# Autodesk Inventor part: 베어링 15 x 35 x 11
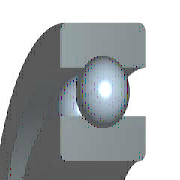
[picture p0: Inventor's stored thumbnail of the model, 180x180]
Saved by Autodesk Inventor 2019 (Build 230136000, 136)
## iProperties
Created: 2012-02
Part Number: 베어링 15 x 35 x 11
Material: 강철, 연강
Description: 깊은 그루브 볼 베어링
Document SubType Name: Modeling
Standard: KS B 2023
Designer: mduedu
Standards Organization: KS
Language: ko-KR
Size Designation: 6202 - 15 x 35 x 11
Categories: <MemberInstance><Categories><Category DisplayName="샤프트 부품" InternalName="7f7aeb1f-a693-4053-b835-cee3144e0d98" Mnemonic="SHFT"><Category DisplayName="베어링" Inter
Density: 1 g/cm^3
Appearance: 밝은 황색
IsCustomPart: 1
Author: mduedu
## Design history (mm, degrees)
sketch "스케치" dims "d0" = 5.2 (= -0.26 x WD + 0.26 x BD)
  geometry: L1 (2.9, 12.5)-(8.1, 12.5); L2 (5.5, 12.5)-(5.5, 9.9); L3 (5.5, 12.5)-(5.5, 15.1); L4 (3.568, 10.76)-(0, 10.76); L5 (0, 7.5)-(11, 7.5); L6 (3.568, 14.24)-(0, 14.24); L7 (0, 17.5)-(11, 17.5); L8 (11, 7.5)-(11, 10.76); L9 (7.432, 10.76)-(11, 10.76); L10 (7.432, 14.24)-(11, 14.24); L11 (11, 17.5)-(11, 14.24); L12 (-1.4, 0)-(8.4, 0) reference; L13 (0, -0.3)-(0, 5.3) reference
  constraints: 22 end point, 4 point on line, 2 collinear, 2 perpendicular, 2 symmetric about line, 1 midpoint, 1 parallel, 14 other
  dimensions: "d9" = 15 diameter of L5 L12 (= WD); "d11" = 35 diameter of L7 L12 (= BD); "d12" = 11 distance between parallel lines of L8 L13 (= KB); "d13" = 21.52 diameter of L9 L12 (= 0.326 x BD + 0.674 x WD)
revolve "본체" stored, may be unused: angle "d6" = 90 deg
revolve "볼" stored, may be unused: angle "d7" = 90 deg
pattern_circular "IDS_ARRAYBALL[SIMPL:T]" dims angle "d3" = 360 deg
body "Solid1"
fillet "모깎기1" dims "d1" = 0.6 (= KRS)
other parameters: "WD" = 15 [user parameter; used in 5 equation terms], "BD" = 35 [user parameter; used in 5 equation terms], "KB" = 11 [user parameter; used in 1 equation term], "KRS" = 0.6 [user parameter; used in 1 equation term], "d4" = 0, "d5" = 0, "d8" = 0, "d14" = 0, "d15" = 0, "BBA" = 0 [user parameter], "BC0" = 3750000 [user parameter], "BC" = 7800000 [user parameter], "BR" = 17.5 (= 0.5 x BD) [user parameter], "WR" = 7.5 (= 0.5 x WD) [user parameter]
